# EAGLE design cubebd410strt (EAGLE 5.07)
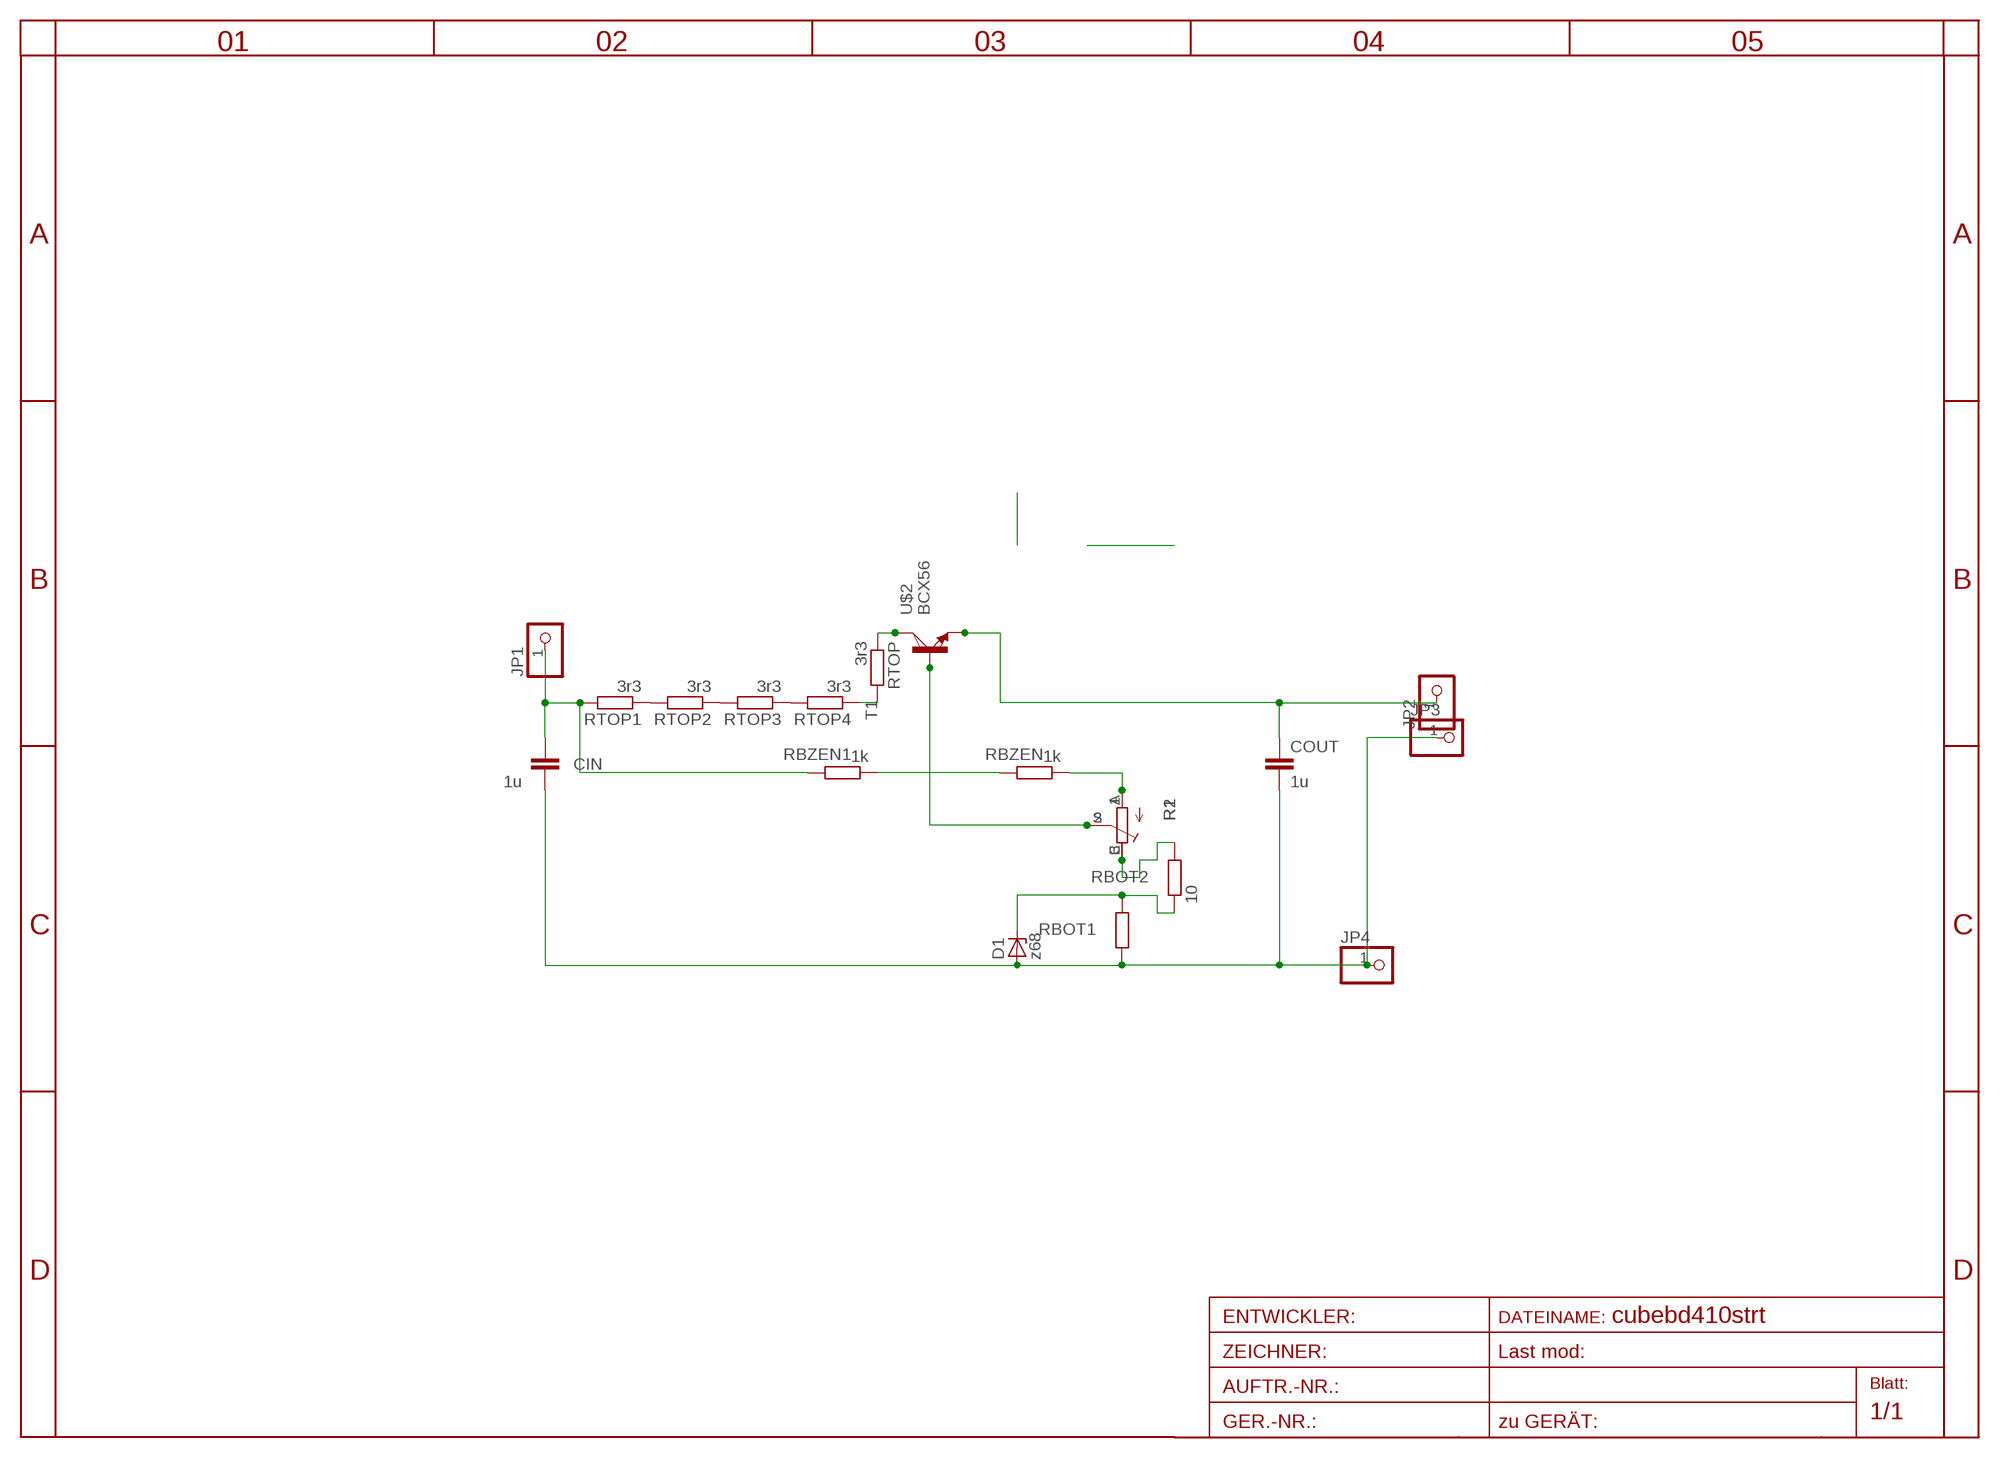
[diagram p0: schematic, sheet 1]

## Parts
CIN  1u  C-EU025-024X044  [C025-024X044]
COUT  1u  C-EU025_050-055X075  [C025_050-055X075]
D1  z68  ZENER-DIODESOD80C  [SOD80C]
JP1  PINHD-1X11X0.4  [1X01]
JP2  PINHD-1X11X0.4  [1X01]
JP3  PINHD-1X11X0.4  [1X01]
JP4  PINHD-1X11X0.4  [1X01]
R1  R-TRIMM3202  [RTRIM3202]
R2  TRIM_EU-CA6V  [CA6V]
RBOT1  R-EU_R0805  [R0805]
RBOT2  10  R-EU_0204/5  [0204/5]
RBZEN  1k  R-EU_0204/2V  [0204V]
RBZEN1  1k  R-EU_0204/2V  [0204V]
RTOP  3r3  R-EU_0204/2V  [0204V]
RTOP1  3r3  R-EU_0204/2V  [0204V]
RTOP2  3r3  R-EU_0204/2V  [0204V]
RTOP3  3r3  R-EU_0204/2V  [0204V]
RTOP4  3r3  R-EU_0204/2V  [0204V]
T1  -NPN-TO126V  [TO126V]
U$2  BCX56  [SOT223]

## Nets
C: RTOP.1 T1.2(C) U$2.2(C)
GND: CIN.2 COUT.2 D1.A JP3.1 JP4.1 RBOT1.1
N$1: RBZEN1.1 RBZEN.2
N$2: RTOP1.1 RTOP2.2
N$4: R1.3(A) R2.E RBOT2.2
N$5: D1.C RBOT1.2 RBOT2.1
N$7: RTOP2.1 RTOP3.2
N$8: RTOP3.1 RTOP4.2
N$9: R1.2(S) R2.S T1.3(B) U$2.1(B)
N$10: R1.1(E) R2.A RBZEN.1
N$11: RTOP4.1 RTOP.2
OUT: COUT.1 JP2.1 T1.1(E) U$2.3(E)
VPLUS: CIN.1 JP1.1 RBZEN1.2 RTOP1.2

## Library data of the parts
CIN COUT = rcl:C-EU: CAPACITOR, European symbol
D1 = diode:ZENER-DIODE: Z-Diode
JP1-JP4 = pinhead:PINHD-1X1: PIN HEADER
R1 = rcl:R-TRIMM: Trimm resistor
R2 = pot:TRIM_EU-: POTENTIOMETER
RBOT1 RBOT2 RBZEN RBZEN1 RTOP RTOP1-RTOP4 = rcl:R-EU_: RESISTOR, European symbol
T1 = transistor:*-NPN-: NPN Transistror BF959 corrected 2008.03.06
U$2 = transistor-power:BCX56

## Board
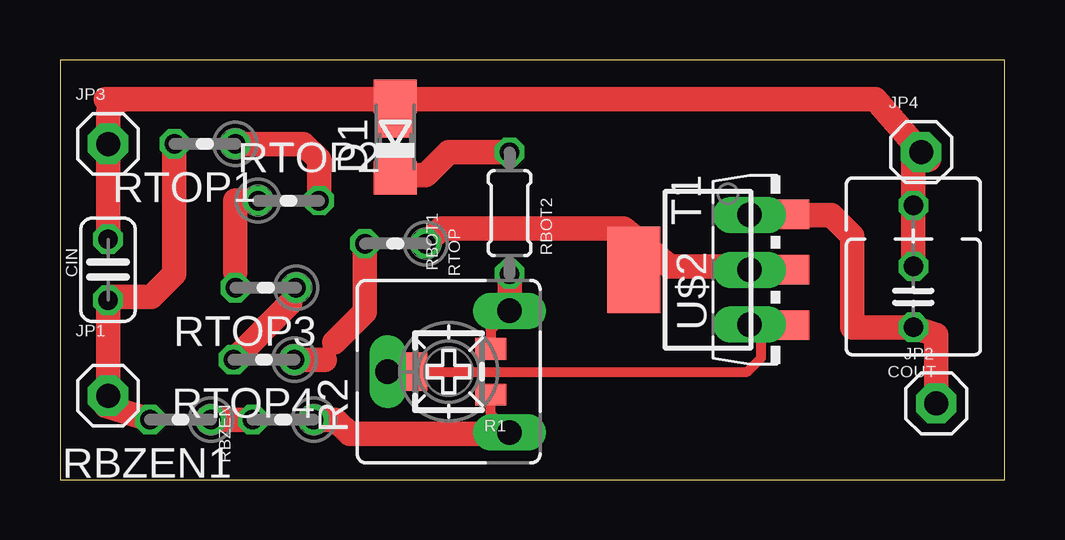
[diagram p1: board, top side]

Size 39.37 x 17.5 mm. Coordinates in mm from the lower left corner, seen from the top.
Outline: 0,0 39.37,0 39.37,17.5 0,17.5 0,0
Copper layers (1*16): Top 0.035mm / dielectric 1.5mm / Bottom 0.035mm
Design rules "default *": minimum track width 10mil, minimum drill 20mil, track to track 8mil, track to pad 8mil, pad to pad 8mil, via to via 8mil, smd to smd 8mil, copper to edge 40mil, drill to drill 8mil, minimum pad ring 1mil, minimum via ring 8mil, stop-mask expansion 4mil, vias tented up to drill 0mil, thermal gap 10mil

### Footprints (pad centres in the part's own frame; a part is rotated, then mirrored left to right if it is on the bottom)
C025-024X044 = drill 0.813 octagon: 1 -1.27,0; 2 1.27,0
C025_050-055X075 = drill 0.813 octagon: 1 -1.27,0; 2 1.27,0; 3 3.81,0
SOD80C = smd 1.4 x 1.8: A 1.7,0; C -1.7,0
1X01 = drill 1 pad 1.676 octagon: 1 0,0
RTRIM3202 = smd 0.9 x 1.3: 1 -0.95,-1.75; 3 0.95,-1.75 | smd 1.6 x 1.4: 2 0,1.6
CA6V = drill 1.016 long: A -2.54,-2.54; E 2.54,-2.54; S 0,2.54
R0805 = smd 1.3 x 1.5: 1 -0.95,0; 2 0.95,0
0204/5 = drill 0.813 octagon: 1 -2.54,0; 2 2.54,0
0204V = drill 0.813 octagon: 1 -1.27,0; 2 1.27,0
TO126V = drill 1.016 long: 1 -2.286,-1.27; 2 0,-1.27; 3 2.286,-1.27
SOT223 = smd 1.219 x 2.235: 1 -2.311,-3.099; 2 0,-3.099; 3 2.311,-3.099 | smd 3.6 x 2.2: 4 0,3.099

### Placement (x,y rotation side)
CIN  2,8.75 90 top
COUT  35.56,7.62 90 top
D1  13.97,14.29 90 top
JP1  2,3.5 0 top
JP2  36.51,3.17 0 top
JP3  2,14 0 top
JP4  35.88,13.65 0 top
R1  16.19,4.5 90 top
R2  16.19,4.5 90 top
RBOT1  13.97,13.97 270 top
RBOT2  18.73,11.11 270 top
RBZEN  9.3,2.5 180 top
RBZEN1  5.02,2.5 180 top
RTOP  13.97,9.84 180 top
RTOP1  6.03,14 180 top
RTOP2  9.53,11.63 0 top
RTOP3  8.57,8 180 top
RTOP4  8.5,5 180 top
T1  30,8.75 270 top
U$2  27,8.75 90 top

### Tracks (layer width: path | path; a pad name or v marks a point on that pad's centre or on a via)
C
  Top 0.406: 27.68,8.89 T1.2
  Top 1.016: RTOP.1 15.88,10.48 23.5,10.48 25.4,8.89 27.68,8.89 | U$2.2 T1.2
GND
  Top 0.406: D1.A 13.65,15.88 RBOT1.1 | CIN.2 2.1,10.48
  Top 1.016: 2.54,15.88 1.91,15.88 | 2.54,15.88 13.65,15.88 33.97,15.88 JP4.1 36.2,13.34 35.56,13.34 35.56,11.11 COUT.2 | CIN.2 JP3.1 2,15.34 2.54,15.88
N$1
  Top 1.016: RBZEN1.1 RBZEN.2
N$2
  Top 1.016: RTOP1.1 10.13,14 10.79,13.34 RTOP2.2
N$4
  Top 0.406: R1.3 17.94,6.25 R2.E
  Top 1.016: R2.E RBOT2.2
N$5
  Top 0.406: D1.C 14.08,12.7 14.08,12.91 RBOT1.2
  Top 1.016: RBOT2.1 16.19,13.65 15.24,12.7 14.08,12.7
N$7
  Top 0.406: 7.3,8.63 RTOP3.2
  Top 1.016: RTOP2.1 7.3,11.63 7.3,8.63
N$8
  Top 0.406: RTOP3.1 9.6,7.37
  Top 1.016: 9.6,7.37 RTOP4.2
N$9
  Top 0.406: T1.3 29.21,5.98 29.21,5.08 28.63,4.5 R1.2 R2.S
  Top 1.016: U$2.1 28.75,6.44 T1.3
N$10
  Top 0.406: R1.1 17.94,2.75 R2.A 18.68,1.91
  Top 1.016: RBZEN.1 11.47,2.5 12.06,1.91 18.68,1.91
N$11
  Top 0.406: 11.03,5 11.11,5.08 11.43,5.71
  Top 1.016: RTOP4.1 11.03,5 | 11.43,5.71 12.7,6.99 RTOP.2
OUT
  Top 1.016: JP2.1 36.51,6.03 COUT.1 33.02,6.35 33.02,10.16 32.14,11.04 T1.1 28.75,11.06 U$2.3
VPLUS
  Top 1.016: RBZEN1.2 1.91,3.06 JP1.1 CIN.1 2.14,7.62 3.81,7.62 4.76,8.57 RTOP1.2

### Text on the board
tStop: MICHAEL5.net
bStop: MICHAEL5.net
